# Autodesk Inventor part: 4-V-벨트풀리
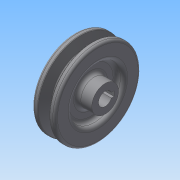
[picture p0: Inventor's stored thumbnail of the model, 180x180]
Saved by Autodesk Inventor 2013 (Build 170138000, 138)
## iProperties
Created: 2015-02
Part Number: 4-V-벨트풀리
Material: 일반
Document SubType Name: Modeling
Designer: Administrator
Density: 1 g/cm^3
Author: Administrator
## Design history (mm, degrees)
sketch "스케치1"
  geometry: L1 (0, 0)-(25, 0); L2 (0, 0)-(0, 11); L3 (0, 11)-(6, 11); L4 (6, 11)-(6, 21.5); L5 (6, 21.5)-(0, 21.5); L6 (0, 21.5)-(0, 35.2); L7 (0, 35.2)-(4.675, 35.2); L8 (11.574, 26.2)-(14.325, 35.2); L9 (14.325, 35.2)-(19, 35.2); L10 (19, 35.2)-(19, 21.5); L11 (19, 21.5)-(13, 21.5); L12 (13, 21.5)-(13, 11); L13 (13, 11)-(25, 11); L14 (25, 11)-(25, 0); L15 (4.675, 35.2)-(7.426, 26.2); L16 (7.426, 26.2)-(11.574, 26.2); 2 further points
  constraints: 32 end point, 6 parallel, 4 collinear, 4 equal length, 3 perpendicular, 2 point on line, 2 vertical, 1 horizontal, 1 horizontal alignment, 1 vertical alignment
  dimensions: "d0" = 25 distance of L1.start L1.end; "d1" = 43 diameter of L5 L1; "d2" = 22 diameter of L13 L1; "d3" = 6 distance of L4.end L5.end; "d4" = 19 distance of L9.end L6.end; "d5" = 8 distance of point (13.5, 32.5) point (5.5, 32.5); "d6" = 34 deg angle of L8 L15; "d7" = 2.7 vertical distance of point (5.5, 32.5) L7.end; "d8" = 6.3 vertical distance of L15.end point (5.5, 32.5); "d9" = 65 diameter of point (5.5, 32.5) L1
revolve "회전1" sketch "스케치1" stored, may be unused: angle "d10" = 90 deg
sketch "스케치2"
  geometry: L1 (-2, 5.123)-(-2, 7.3); L2 (-2, 7.3)-(2, 7.3); L3 (2, 7.3)-(2, 5.123); C1 r 11 at (0, 0) reference; A1 r 5.5 centre (0, 0) between (-2, 5.123) and (2, 5.123); 2 further points
  constraints: 6 end point, 3 point on circle, 2 vertical alignment, 1 centre point, 1 coincident, 1 midpoint, 1 parallel, 1 perpendicular, 1 vertical
  dimensions: "d11" = 11 diameter of A1; "d13" = 4 distance of L1.end L2.end; "d14" = 12.8 distance from line of point (0, -5.5) L2
extrude "돌출1" cut sketch "스케치2" stored distance "d15" = 10; taper "d16" = 0 deg
fillet "모깎기1" dims "d17" = 1, "d18" = 0.5, "d19" = 2
fillet "모깎기2" dims "d20" = 3
node "솔리드1"
